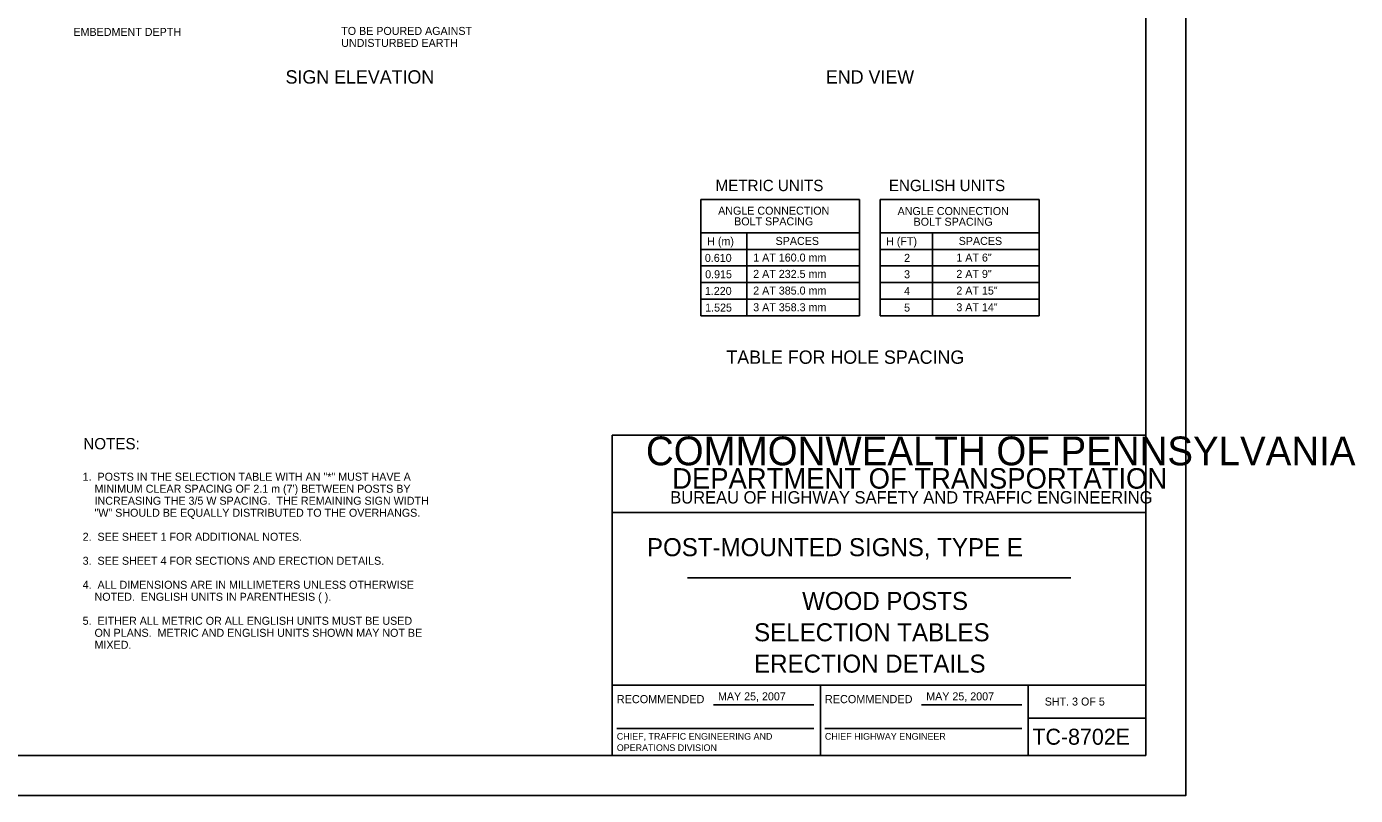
# Model space of a CAD drawing. Extents: x -1958 to 628, y -879 to 309.
# Drawn here: x 130.1 to 628.2, y -284.6 to 3.6 of the extents above; entities that cross this region are included whole.
import ezdxf

# ---------------------------------------------------------------- set-up
doc = ezdxf.new("R2010")
doc.units = 0
for name, color, linetype in [('1', 7, 'Continuous'), ('2', 7, 'Continuous'), ('3', 7, 'Continuous'), ('4', 7, 'Continuous'), ('PLT-BNDY', 7, 'Continuous')]:
    doc.layers.add(name, color=color, linetype=linetype)

msp = doc.modelspace()

# ---------------------------------------------------------------- linework, layer by layer
at = {"layer": '1'}
for p, q in [((549.61, -269.56), (549.61, 294.44)), ((349.61, -269.56), (349.61, -149.56)), ((349.61, -149.56), (549.61, -149.56)), ((549.61, -178.56), (349.61, -178.56)), ((377.86, -203.06), (521.49, -203.06)), ((349.61, -243.19), (549.61, -243.19)), ((427.61, -243.19), (427.61, -269.56)), ((505.49, -269.56), (505.49, -243.19)), ((387.55, -250.62), (425.17, -250.62)), ((465.55, -250.62), (503.17, -250.62)), ((505.49, -255.56), (549.61, -255.56)), ((351.3, -259.51), (425.17, -259.51)), ((429.3, -259.51), (503.17, -259.51)), ((549.61, -269.56), (-236.39, -269.56)), ((-236.39, -269.56), (349.61, -269.56))]:
    msp.add_line(p, q, dxfattribs=at)
at = {"layer": '2'}
for p, q in [((442.31, -61.22), (382.81, -61.22)), ((382.81, -104.84), (382.81, -61.22)), ((442.31, -104.84), (442.31, -61.22)), ((509.58, -61.22), (450.08, -61.22)), ((450.08, -104.84), (450.08, -61.22)), ((509.58, -104.84), (509.58, -61.22)), ((442.31, -73.72), (382.81, -73.72)), ((400.06, -104.84), (400.06, -73.72)), ((509.58, -73.72), (450.08, -73.72)), ((469.64, -104.84), (469.64, -73.72)), ((442.31, -79.97), (382.81, -79.97)), ((509.58, -79.97), (450.08, -79.97)), ((442.31, -86.09), (382.81, -86.09)), ((509.58, -86.09), (450.08, -86.09)), ((442.31, -92.34), (382.81, -92.34)), ((509.58, -92.34), (450.08, -92.34)), ((442.31, -98.59), (382.81, -98.59)), ((509.58, -98.59), (450.08, -98.59)), ((442.31, -104.84), (382.81, -104.84)), ((509.58, -104.84), (450.08, -104.84))]:
    msp.add_line(p, q, dxfattribs=at)
at = {"layer": 'PLT-BNDY'}
msp.add_lwpolyline([(-276.39, 309.44), (564.61, 309.44), (564.61, -284.56), (-276.39, -284.56)], close=True, dxfattribs=at)

# ---------------------------------------------------------------- texts
at = {"layer": '1'}
for s, height, p in [('COMMONWEALTH OF PENNSYLVANIA', 10.7827, (362.21, -160.83)), ('DEPARTMENT OF TRANSPORTATION', 7.6838, (372.07, -169.58)), ('BUREAU OF HIGHWAY SAFETY AND TRAFFIC ENGINEERING', 4.6252, (371.34, -175.15)), ('POST-MOUNTED SIGNS, TYPE E', 6.7492, (362.61, -194.89)), ('WOOD POSTS', 6.75, (420.77, -215.04)), ('SELECTION TABLES', 6.75, (402.77, -226.79)), ('ERECTION DETAILS', 6.75, (402.77, -238.54)), ('RECOMMENDED', 3.048, (351.3, -249.99)), ('RECOMMENDED', 3.048, (429.3, -249.99)), ('SHT. 3 OF 5', 3, (511.7, -250.88)), ('CHIEF, TRAFFIC ENGINEERING AND', 2.5, (351.3, -263.68)), ('CHIEF HIGHWAY ENGINEER', 2.5, (429.3, -263.68)), ('TC-8702E', 6, (507.09, -265.56)), ('OPERATIONS DIVISION', 2.5, (351.3, -267.93))]:
    msp.add_text(s, height=height, dxfattribs=at).set_placement(p)
at = {"layer": '2'}
for s, height, p in [('METRIC UNITS', 4.25, (388.32, -58.06)), ('ENGLISH UNITS', 4.25, (453.28, -58.06)), ('MAY 25, 2007', 3, (389.22, -248.93)), ('MAY 25, 2007', 3, (467.29, -248.93))]:
    msp.add_text(s, height=height, dxfattribs=at).set_placement(p)
at = {"layer": '3'}
for s, height, p in [('EMBEDMENT DEPTH', 3, (147.62, 0.1)), ('TO BE POURED AGAINST ', 3, (248, 0.48)), ('UNDISTURBED EARTH', 3, (248, -4.02)), ('SIGN ELEVATION', 5, (227.14, -17.77)), ('END VIEW', 5, (429.68, -17.77)), ('ANGLE CONNECTION', 3, (389.28, -66.89)), ('ANGLE CONNECTION', 3, (456.55, -67.04)), ('BOLT SPACING', 3, (395.28, -70.9)), ('BOLT SPACING', 3, (462.55, -71.04)), ('H (m)', 3, (385.18, -78.34)), ('SPACES', 3, (410.81, -78.23)), ('H (FT)', 3, (452.24, -78.34)), ('SPACES', 3, (479.45, -78.23)), ('0.610', 3, (384.31, -84.59)), ('1 AT 160.0 mm', 3, (402.43, -84.47)), ('2', 3, (458.99, -84.59)), ('1 AT 6"', 3, (478.58, -84.47)), ('0.915', 3, (384.43, -90.72)), ('2 AT 232.5 mm', 3, (402.43, -90.59)), ('3', 3, (458.99, -90.72)), ('2 AT 9"', 3, (478.58, -90.59)), ('1.220', 3, (384.31, -96.97)), ('2 AT 385.0 mm', 3, (402.43, -96.84)), ('4', 3, (458.99, -96.97)), ('2 AT 15"', 3, (478.58, -96.84)), ('1.525', 3, (384.43, -103.22)), ('3 AT 358.3 mm', 3, (402.43, -103.09)), ('5', 3, (458.99, -103.22)), ('3 AT 14"', 3, (478.58, -103.09)), ('TABLE FOR HOLE SPACING', 5, (392.37, -122.79)), ('NOTES:', 4.25, (151.34, -154.85))]:
    msp.add_text(s, height=height, dxfattribs=at).set_placement(p)
at = {"layer": '4'}
for s, p in [('1.  POSTS IN THE SELECTION TABLE WITH AN "*" MUST HAVE A', (151.08, -166.61)), ("    MINIMUM CLEAR SPACING OF 2.1 m (7') BETWEEN POSTS BY", (151.08, -171.11)), ('    INCREASING THE 3/5 W SPACING.  THE REMAINING SIGN WIDTH', (151.08, -175.61)), ('    "W" SHOULD BE EQUALLY DISTRIBUTED TO THE OVERHANGS.', (151.08, -180.11)), ('2.  SEE SHEET 1 FOR ADDITIONAL NOTES.', (151.08, -189.11)), ('3.  SEE SHEET 4 FOR SECTIONS AND ERECTION DETAILS.', (151.08, -198.11)), ('4.  ALL DIMENSIONS ARE IN MILLIMETERS UNLESS OTHERWISE', (151.08, -207.11)), ('    NOTED.  ENGLISH UNITS IN PARENTHESIS ( ).', (151.08, -211.61)), ('5.  EITHER ALL METRIC OR ALL ENGLISH UNITS MUST BE USED', (151.08, -220.61)), ('    ON PLANS.  METRIC AND ENGLISH UNITS SHOWN MAY NOT BE', (151.08, -225.11)), ('    MIXED.', (151.08, -229.61))]:
    msp.add_text(s, height=3, dxfattribs=at).set_placement(p)

doc.saveas('drawing.dxf')
